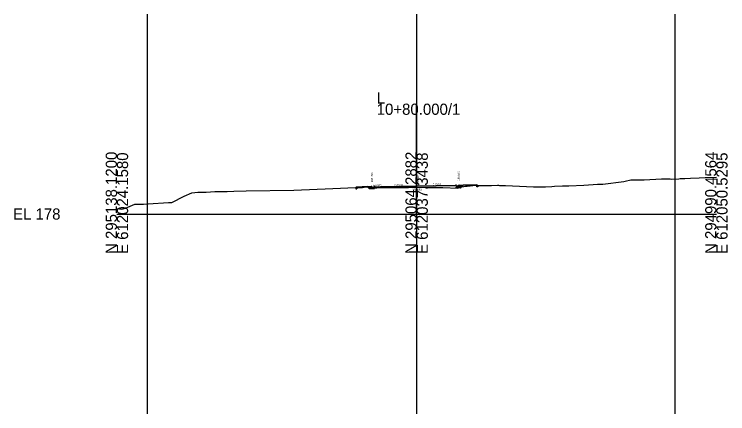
# Model space of a CAD drawing. Extents: x -81 to 616364, y 450 to 299952.
# Drawn here: x 535426.7 to 535605.2, y 116798.4 to 116898.4 of the extents above; entities that cross this region are included whole.
import ezdxf

# ---------------------------------------------------------------- set-up
doc = ezdxf.new("R2010")
doc.units = 0
for name, color, linetype in [('Exist XS Ground Line', 7, 'Continuous'), ('Old_Level_10', 7, 'Continuous'), ('Old_Level_17', 7, 'Continuous'), ('Old_Level_63', 7, 'Continuous'), ('Prop XS Dump Level', 7, 'Continuous'), ('Prop XS Earthwork Shape', 7, 'Continuous'), ('Prop XS EOT Tick Mark', 7, 'Continuous'), ('Prop XS Exc Vertical Line 1', 7, 'Continuous'), ('Prop XS Exc Vertical Line 2', 7, 'Continuous'), ('Prop XS Exc Vertical Line 3', 7, 'Continuous'), ('Prop XS Finish Grade', 7, 'Continuous'), ('Prop XS Finish Grade Concrete', 7, 'Continuous'), ('Prop XS Finish Grade Earthwork', 7, 'Continuous'), ('Prop XS Finish Grade Pavement', 7, 'Continuous'), ('Prop XS Pvmt Edge Slope', 7, 'Continuous'), ('Prop XS Side Slope Text', 7, 'Continuous'), ('Prop XS Subgrade Concrete', 7, 'Continuous'), ('Prop XS Subgrade Earthwork', 7, 'Continuous')]:
    doc.layers.add(name, color=color, linetype=linetype)

msp = doc.modelspace()

# ---------------------------------------------------------------- linework, layer by layer
at = {"layer": 'Exist XS Ground Line'}
for points in [[(535569.21, 116855.6), (535571.5, 116855.72), (535572.6, 116855.85), (535573.91, 116855.87), (535579.24, 116856.48), (535579.58, 116856.57), (535580.96, 116856.91), (535581.17, 116856.91), (535583.06, 116856.89), (535583.31, 116856.9), (535584.28, 116856.93), (535588.6, 116857.13), (535589.69, 116857.17), (535589.86, 116857.17), (535590.06, 116857.18), (535590.29, 116857.18), (535590.84, 116857.14), (535591.2, 116857.12), (535592.94, 116857.2), (535593.27, 116857.22), (535593.77, 116857.24), (535594.5, 116857.27), (535595.87, 116857.34), (535598.07, 116857.44), (535599.56, 116857.51), (535602.36, 116857.57)], [(535452.36, 116849.77), (535453.63, 116849.59), (535454.49, 116849.86), (535456.86, 116850.82), (535457.5, 116850.83), (535458.99, 116850.84), (535460.17, 116850.87), (535465.23, 116851.22), (535466.09, 116851.24), (535469.18, 116852.83), (535471.08, 116853.7), (535472.6, 116853.82), (535474.71, 116853.87), (535476.87, 116854), (535478.77, 116854.01), (535479.97, 116854.02), (535481.62, 116854.04), (535484.7, 116854.15), (535496.66, 116854.35), (535502.46, 116854.62), (535504.5, 116854.7), (535506.39, 116854.72), (535512.08, 116854.96), (535512.3, 116854.97), (535512.56, 116854.95), (535513.85, 116854.97), (535514.26, 116855.09), (535515.44, 116855.14), (535515.72, 116855.12), (535516.27, 116855.07), (535516.48, 116855.04), (535516.78, 116855.02), (535517.03, 116854.91), (535520.34, 116854.98), (535521.22, 116854.99), (535524.78, 116855.04), (535525.13, 116855.04), (535525.32, 116855.04), (535527.2, 116855.05), (535527.36, 116855.05), (535529.48, 116855.04), (535529.59, 116855.04), (535533.35, 116855.01), (535533.9, 116855), (535537.67, 116854.86), (535537.85, 116855.04), (535539.56, 116855.31), (535539.79, 116855.34), (535540, 116855.35), (535542.14, 116855.58), (535542.29, 116855.48), (535546.12, 116855.53), (535547.6, 116855.57), (535547.87, 116855.57), (535548.07, 116855.53), (535548.48, 116855.51), (535549.58, 116855.47), (535556.56, 116855.2), (535558.68, 116855.13), (535559.58, 116855.18), (535561.17, 116855.29), (535561.83, 116855.32), (535563.89, 116855.38), (535565.45, 116855.4), (535569.21, 116855.6)]]:
    msp.add_lwpolyline(points, dxfattribs=at)
at = {"layer": 'Old_Level_10'}
for p, q in [((535512.37, 116854.97), (535512.37, 116855.09)), ((535542.45, 116855.49), (535542.45, 116855.63))]:
    msp.add_line(p, q, dxfattribs=at)
at = {"layer": 'Old_Level_17'}
for p, q in [((535512.29, 116855.08), (535512.17, 116854.97)), ((535512.17, 116854.97), (535512.17, 116854.64)), ((535512.37, 116854.94), (535512.17, 116854.94)), ((535512.17, 116854.88), (535512.19, 116854.89)), ((535512.18, 116854.87), (535512.17, 116854.87)), ((535512.18, 116854.8), (535512.17, 116854.8)), ((535512.17, 116854.78), (535512.19, 116854.77)), ((535512.17, 116854.64), (535512.37, 116854.64)), ((535512.19, 116854.89), (535512.18, 116854.87)), ((535512.19, 116854.77), (535512.18, 116854.8)), ((535512.24, 116854.98), (535512.27, 116854.99)), ((535512.28, 116854.97), (535512.24, 116854.98)), ((535512.24, 116854.69), (535512.27, 116854.7)), ((535512.28, 116854.68), (535512.24, 116854.69)), ((535512.27, 116854.99), (535512.28, 116854.97)), ((535512.27, 116854.7), (535512.28, 116854.68)), ((535512.29, 116855.08), (535512.29, 116855.08)), ((535512.37, 116855.09), (535512.32, 116855.09)), ((535512.36, 116855.09), (535512.35, 116855.08)), ((535512.35, 116855.08), (535512.37, 116855.07)), ((535512.35, 116854.9), (535512.37, 116854.91)), ((535512.37, 116854.88), (535512.35, 116854.9)), ((535512.36, 116854.81), (535512.35, 116854.78)), ((535512.35, 116854.78), (535512.37, 116854.78)), ((535512.37, 116854.79), (535512.36, 116854.81)), ((535512.37, 116855.08), (535512.37, 116855.09)), ((535512.37, 116854.97), (535512.37, 116854.64)), ((535542.45, 116855.63), (535542.46, 116855.64)), ((535542.48, 116855.62), (535542.45, 116855.62)), ((535542.45, 116855.49), (535542.65, 116855.49)), ((535542.45, 116855.19), (535542.45, 116855.49)), ((535542.45, 116855.43), (535542.48, 116855.45)), ((535542.48, 116855.45), (535542.45, 116855.45)), ((535542.45, 116855.34), (535542.47, 116855.36)), ((535542.48, 116855.33), (535542.45, 116855.33)), ((535542.65, 116855.19), (535542.45, 116855.19)), ((535542.46, 116855.64), (535542.51, 116855.64)), ((535542.47, 116855.64), (535542.48, 116855.62)), ((535542.47, 116855.36), (535542.48, 116855.33)), ((535542.54, 116855.62), (535542.65, 116855.51)), ((535542.54, 116855.62), (535542.54, 116855.62)), ((535542.56, 116855.54), (535542.55, 116855.51)), ((535542.55, 116855.51), (535542.59, 116855.53)), ((535542.56, 116855.25), (535542.55, 116855.22)), ((535542.55, 116855.22), (535542.59, 116855.23)), ((535542.59, 116855.53), (535542.56, 116855.54)), ((535542.59, 116855.23), (535542.56, 116855.25)), ((535542.63, 116855.32), (535542.65, 116855.34)), ((535542.65, 116855.32), (535542.63, 116855.32)), ((535542.64, 116855.43), (535542.65, 116855.41)), ((535542.65, 116855.43), (535542.64, 116855.43)), ((535542.65, 116855.51), (535542.65, 116855.19)), ((535542.65, 116855.41), (535542.65, 116855.41)), ((535542.65, 116855.34), (535542.65, 116855.34))]:
    msp.add_line(p, q, dxfattribs=at)
for centre in [(535512.18, 116854.83), (535512.2, 116854.95), (535512.2, 116854.66), (535512.22, 116854.99), (535512.21, 116854.84), (535512.22, 116854.7), (535512.23, 116854.95), (535512.22, 116854.9), (535512.22, 116854.75), (535512.23, 116854.66), (535512.25, 116854.8), (535512.26, 116855.02), (535512.27, 116854.93), (535512.26, 116854.73), (535512.27, 116855.05), (535512.27, 116854.89), (535512.27, 116854.85), (535512.28, 116854.84), (535512.27, 116854.76), (535512.28, 116854.8), (535512.3, 116855.03), (535512.3, 116854.97), (535512.3, 116854.88), (535512.3, 116854.74), (535512.3, 116854.68), (535512.32, 116854.93), (535512.33, 116854.84), (535512.32, 116854.82), (535512.35, 116854.99), (535512.35, 116854.7), (535512.35, 116855.03), (535512.35, 116854.74), (535512.36, 116854.86), (535542.47, 116855.4), (535542.48, 116855.58), (535542.48, 116855.54), (535542.48, 116855.29), (535542.48, 116855.25), (535542.5, 116855.39), (535542.51, 116855.48), (535542.51, 116855.36), (535542.53, 116855.43), (535542.53, 116855.57), (535542.53, 116855.52), (535542.53, 116855.28), (535542.53, 116855.22), (535542.56, 116855.6), (535542.55, 116855.38), (535542.55, 116855.34), (535542.56, 116855.3), (535542.56, 116855.48), (535542.56, 116855.43), (535542.56, 116855.4), (535542.57, 116855.57), (535542.57, 116855.28), (535542.58, 116855.35), (535542.6, 116855.49), (535542.6, 116855.2), (535542.61, 116855.54), (535542.61, 116855.45), (535542.61, 116855.29), (535542.61, 116855.25), (535542.62, 116855.39), (535542.63, 116855.5), (535542.63, 116855.21), (535542.65, 116855.38)]:
    msp.add_circle(centre, 0.00196, dxfattribs=at)
for centre, radius, start, end in [((535512.18, 116854.74), 0.00196, 256.8767, 103.1233), ((535512.27, 116854.64), 0.00196, 24.915, 155.085), ((535512.32, 116855.04), 0.05, 90, 135), ((535512.32, 116854.64), 0.00196, 342.3416, 197.6584), ((535512.37, 116855.09), 0.006, 359.8812, 90), ((535512.38, 116855.04), 0.00196, 145.5013, 214.4987), ((535512.37, 116854.83), 0.00196, 17.8106, 342.1894), ((535542.46, 116855.63), 0.006, 90, 180), ((535542.45, 116855.58), 0.00196, 325.5013, 34.4987), ((535542.46, 116855.38), 0.00196, 197.8106, 162.1894), ((535542.51, 116855.59), 0.05, 45, 90), ((535542.51, 116855.19), 0.00196, 342.3416, 197.6584), ((535542.56, 116855.19), 0.00196, 24.915, 155.085), ((535542.65, 116855.28), 0.00196, 76.8767, 283.1233)]:
    msp.add_arc(centre, radius, start, end, dxfattribs=at)
at = {"layer": 'Old_Level_63'}
for p, q in [((535527.36, 116848.36), (535527.36, 116875.99)), ((535452.36, 116848.36), (535527.36, 116848.36)), ((535527.36, 116848.36), (535602.36, 116848.36))]:
    msp.add_line(p, q, dxfattribs=at)
at = {"layer": 'Prop XS Dump Level'}
for p, q in [((535516.76, 116855.09), (535518.36, 116855.13)), ((535518.36, 116855.13), (535527.36, 116855.31)), ((535527.36, 116855.31), (535537.26, 116855.46))]:
    msp.add_line(p, q, dxfattribs=at)
at = {"layer": 'Prop XS Earthwork Shape'}
for points in [[(535512.37, 116854.97), (535512.56, 116854.95), (535513.85, 116854.97), (535514.26, 116855.09), (535515.1, 116855.13), (535514.99, 116855.24), (535512.37, 116855.09)], [(535512.37, 116854.97), (535512.56, 116854.95), (535513.85, 116854.97), (535514.26, 116855.09), (535515.1, 116855.13), (535514.99, 116855.24), (535512.37, 116855.09)], [(535512.37, 116854.97), (535512.56, 116854.95), (535513.85, 116854.97), (535514.26, 116855.09), (535515.1, 116855.13), (535514.99, 116855.24), (535512.37, 116855.09)], [(535512.37, 116854.97), (535512.56, 116854.95), (535513.85, 116854.97), (535514.26, 116855.09), (535515.1, 116855.13), (535514.99, 116855.24), (535512.37, 116855.09)], [(535512.37, 116854.97), (535512.56, 116854.95), (535513.85, 116854.97), (535514.26, 116855.09), (535515.1, 116855.13), (535514.99, 116855.24), (535512.37, 116855.09)], [(535512.37, 116854.97), (535512.56, 116854.95), (535513.85, 116854.97), (535514.26, 116855.09), (535515.1, 116855.13), (535514.99, 116855.24), (535512.37, 116855.09)], [(535512.37, 116854.97), (535512.56, 116854.95), (535513.85, 116854.97), (535514.26, 116855.09), (535515.1, 116855.13), (535514.99, 116855.24), (535512.37, 116855.09)], [(535515.51, 116854.71), (535516.76, 116854.71), (535516.84, 116854.72), (535516.85, 116855), (535516.78, 116855.02), (535516.48, 116855.04), (535516.27, 116855.07), (535515.72, 116855.12), (535515.44, 116855.14), (535515.1, 116855.13)], [(535515.51, 116854.71), (535516.76, 116854.71), (535516.84, 116854.72), (535516.85, 116855), (535516.78, 116855.02), (535516.48, 116855.04), (535516.27, 116855.07), (535515.72, 116855.12), (535515.44, 116855.14), (535515.1, 116855.13)], [(535515.51, 116854.71), (535516.76, 116854.71), (535516.84, 116854.72), (535516.85, 116855), (535516.78, 116855.02), (535516.48, 116855.04), (535516.27, 116855.07), (535515.72, 116855.12), (535515.44, 116855.14), (535515.1, 116855.13)], [(535515.1, 116855.13), (535515.44, 116855.14), (535515.72, 116855.12), (535516.27, 116855.07), (535516.48, 116855.04), (535516.78, 116855.02), (535516.85, 116855), (535516.84, 116854.72), (535516.76, 116854.71), (535515.51, 116854.71)], [(535515.51, 116854.71), (535516.76, 116854.71), (535516.84, 116854.72), (535516.85, 116855), (535516.78, 116855.02), (535516.48, 116855.04), (535516.27, 116855.07), (535515.72, 116855.12), (535515.44, 116855.14), (535515.1, 116855.13)], [(535515.51, 116854.71), (535516.76, 116854.71), (535516.84, 116854.72), (535516.85, 116855), (535516.78, 116855.02), (535516.48, 116855.04), (535516.27, 116855.07), (535515.72, 116855.12), (535515.44, 116855.14), (535515.1, 116855.13)], [(535515.51, 116854.71), (535516.76, 116854.71), (535516.84, 116854.72), (535516.85, 116855), (535516.78, 116855.02), (535516.48, 116855.04), (535516.27, 116855.07), (535515.72, 116855.12), (535515.44, 116855.14), (535515.1, 116855.13)], [(535537.26, 116854.88), (535537.67, 116854.86), (535537.85, 116855.04), (535538.28, 116855.11), (535537.26, 116855.08)], [(535537.26, 116855.08), (535538.28, 116855.11), (535537.85, 116855.04), (535537.67, 116854.86), (535537.26, 116854.88)], [(535537.26, 116855.08), (535538.28, 116855.11), (535537.85, 116855.04), (535537.67, 116854.86), (535537.26, 116854.88)], [(535537.26, 116854.88), (535537.67, 116854.86), (535537.85, 116855.04), (535538.28, 116855.11), (535537.26, 116855.08)], [(535537.26, 116854.88), (535537.67, 116854.86), (535537.85, 116855.04), (535538.28, 116855.11), (535537.26, 116855.08)], [(535537.26, 116854.88), (535537.67, 116854.86), (535537.85, 116855.04), (535538.28, 116855.11), (535537.26, 116855.08)], [(535537.26, 116855.08), (535538.28, 116855.11), (535537.85, 116855.04), (535537.67, 116854.86), (535537.26, 116854.88)], [(535538.28, 116855.11), (535538.55, 116855.15), (535538.51, 116855.12)], [(535538.28, 116855.11), (535538.55, 116855.15), (535538.51, 116855.12)], [(535538.28, 116855.11), (535538.55, 116855.15), (535538.51, 116855.12)], [(535538.28, 116855.11), (535538.55, 116855.15), (535538.51, 116855.12)], [(535538.28, 116855.11), (535538.55, 116855.15), (535538.51, 116855.12)], [(535538.28, 116855.11), (535538.55, 116855.15), (535538.51, 116855.12)], [(535538.28, 116855.11), (535538.55, 116855.15), (535538.51, 116855.12)], [(535538.55, 116855.15), (535539.56, 116855.31), (535539.79, 116855.34), (535540, 116855.35), (535542.14, 116855.58), (535542.29, 116855.48), (535542.45, 116855.49), (535542.45, 116855.63), (535539.02, 116855.62)], [(535538.55, 116855.15), (535539.56, 116855.31), (535539.79, 116855.34), (535540, 116855.35), (535542.14, 116855.58), (535542.29, 116855.48), (535542.45, 116855.49), (535542.45, 116855.63), (535539.02, 116855.62)], [(535538.55, 116855.15), (535539.56, 116855.31), (535539.79, 116855.34), (535540, 116855.35), (535542.14, 116855.58), (535542.29, 116855.48), (535542.45, 116855.49), (535542.45, 116855.63), (535539.02, 116855.62)], [(535538.55, 116855.15), (535539.56, 116855.31), (535539.79, 116855.34), (535540, 116855.35), (535542.14, 116855.58), (535542.29, 116855.48), (535542.45, 116855.49), (535542.45, 116855.63), (535539.02, 116855.62)], [(535538.55, 116855.15), (535539.56, 116855.31), (535539.79, 116855.34), (535540, 116855.35), (535542.14, 116855.58), (535542.29, 116855.48), (535542.45, 116855.49), (535542.45, 116855.63), (535539.02, 116855.62)], [(535538.55, 116855.15), (535539.56, 116855.31), (535539.79, 116855.34), (535540, 116855.35), (535542.14, 116855.58), (535542.29, 116855.48), (535542.45, 116855.49), (535542.45, 116855.63), (535539.02, 116855.62)], [(535538.55, 116855.15), (535539.56, 116855.31), (535539.79, 116855.34), (535540, 116855.35), (535542.14, 116855.58), (535542.29, 116855.48), (535542.45, 116855.49), (535542.45, 116855.63), (535539.02, 116855.62)]]:
    msp.add_lwpolyline(points, close=True, dxfattribs=at)
at = {"layer": 'Prop XS EOT Tick Mark'}
for p, q in [((535516.76, 116855.4), (535516.76, 116855.09)), ((535537.26, 116855.46), (535537.26, 116855.76))]:
    msp.add_line(p, q, dxfattribs=at)
at = {"layer": 'Prop XS Exc Vertical Line 1'}
msp.add_line((535459.94, 116898.36), (535459.94, 116798.36), dxfattribs=at)
at = {"layer": 'Prop XS Exc Vertical Line 2'}
msp.add_line((535527.36, 116898.36), (535527.36, 116798.36), dxfattribs=at)
at = {"layer": 'Prop XS Exc Vertical Line 3'}
msp.add_line((535591.96, 116898.36), (535591.96, 116798.36), dxfattribs=at)
at = {"layer": 'Prop XS Finish Grade'}
for p, q in [((535514.99, 116855.24), (535516.01, 116855.22)), ((535538.01, 116855.6), (535539.02, 116855.62))]:
    msp.add_line(p, q, dxfattribs=at)
at = {"layer": 'Prop XS Finish Grade Concrete'}
for p, q in [((535516.09, 116855.22), (535516.01, 116855.22)), ((535516.13, 116855.21), (535516.09, 116855.22)), ((535516.13, 116855.21), (535516.15, 116855.18)), ((535516.15, 116855.18), (535516.18, 116855.11)), ((535516.18, 116855.11), (535516.2, 116855.08)), ((535516.2, 116855.08), (535516.24, 116855.07)), ((535516.24, 116855.07), (535516.76, 116855.09)), ((535537.26, 116855.46), (535537.79, 116855.45)), ((535537.79, 116855.45), (535537.83, 116855.46)), ((535537.83, 116855.46), (535537.85, 116855.49)), ((535537.85, 116855.49), (535537.87, 116855.56)), ((535537.87, 116855.56), (535537.9, 116855.59)), ((535537.94, 116855.6), (535537.9, 116855.59)), ((535538.01, 116855.6), (535537.94, 116855.6))]:
    msp.add_line(p, q, dxfattribs=at)
at = {"layer": 'Prop XS Finish Grade Earthwork'}
for p, q in [((535512.37, 116855.09), (535514.99, 116855.24)), ((535512.37, 116855.09), (535512.37, 116854.97)), ((535539.02, 116855.62), (535542.45, 116855.63)), ((535542.45, 116855.63), (535542.45, 116855.49))]:
    msp.add_line(p, q, dxfattribs=at)
at = {"layer": 'Prop XS Finish Grade Pavement'}
for p, q in [((535518.36, 116855.13), (535516.76, 116855.09)), ((535527.36, 116855.31), (535518.36, 116855.13)), ((535537.26, 116855.46), (535527.36, 116855.31))]:
    msp.add_line(p, q, dxfattribs=at)
at = {"layer": 'Prop XS Pvmt Edge Slope'}
for p, q in [((535515.51, 116854.71), (535515.71, 116854.91)), ((535515.71, 116854.91), (535516.01, 116854.91)), ((535538.01, 116855.3), (535538.31, 116855.31)), ((535538.31, 116855.31), (535538.51, 116855.12))]:
    msp.add_line(p, q, dxfattribs=at)
at = {"layer": 'Prop XS Subgrade Concrete'}
for p, q in [((535516.01, 116855.22), (535516.01, 116854.91)), ((535516.01, 116854.91), (535516.76, 116854.91)), ((535516.76, 116854.91), (535516.76, 116855.09)), ((535537.26, 116855.46), (535537.26, 116855.28)), ((535537.26, 116855.28), (535538.01, 116855.3)), ((535538.01, 116855.3), (535538.01, 116855.6))]:
    msp.add_line(p, q, dxfattribs=at)
at = {"layer": 'Prop XS Subgrade Earthwork'}
for p, q in [((535514.99, 116855.24), (535515.51, 116854.71)), ((535515.51, 116854.71), (535516.76, 116854.71)), ((535516.76, 116854.71), (535516.84, 116854.72)), ((535516.85, 116855), (535516.84, 116854.72)), ((535537.26, 116855.08), (535538.51, 116855.12)), ((535537.26, 116855.08), (535537.26, 116854.88)), ((535538.51, 116855.12), (535539.02, 116855.62))]:
    msp.add_line(p, q, dxfattribs=at)

# ---------------------------------------------------------------- texts
at = {"layer": 'Old_Level_63'}
for s, p in [('L', (535517.36, 116875.99)), ('10+80.000/1', (535517.37, 116873.19)), ('EL 178', (535426.37, 116846.96))]:
    msp.add_text(s, height=2.8, dxfattribs=at).set_placement(p)
for s, p in [('N 295138.1200', (535452.36, 116838.36)), ('E 612024.1580', (535455.16, 116838.37)), ('N 295064.2882', (535527.36, 116838.36)), ('E 612037.3438', (535530.16, 116838.36)), ('N 294990.4564', (535602.36, 116838.36)), ('E 612050.5295', (535605.16, 116838.36))]:
    msp.add_text(s, height=2.8, rotation=90, dxfattribs=at).set_placement(p)
at = {"layer": 'Prop XS Dump Level'}
for p in [(535516.84, 116854.7), (535537.85, 116854.74)]:
    msp.add_text('Eop', height=0.3, dxfattribs=at).set_placement(p)
at = {"layer": 'Prop XS Side Slope Text'}
for s, rotation, p in [('184.705', 90, (535516.41, 116856.29)), (' 184.940', 90, (535527.86, 116855.31)), ('185.087', 90, (535538.11, 116856.67)), ('0.0151', 0.8665, (535531.39, 116855.52)), ('0.0200', 1.1458, (535516.49, 116855.24)), ('0.0200', 1.1458, (535521.79, 116855.35))]:
    msp.add_text(s, height=0.5, rotation=rotation, dxfattribs=at).set_placement(p)
msp.add_text('184.688', height=0.5, dxfattribs=at).set_placement((535526.16, 116854.19))

doc.saveas('drawing.dxf')
